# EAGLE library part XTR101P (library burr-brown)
BURR-BROWN
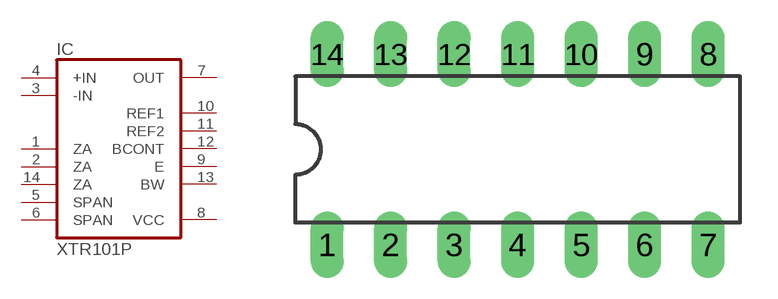
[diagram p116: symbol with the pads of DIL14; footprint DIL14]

Designator prefix IC

## XTR101P (MF: TEXAS INSTRUMENTS; MPN: XTR101AP; OC_FARNELL: 1648756; OC_NEWARK: 84K4518)  [DIL14]
1  ZA  pas
2  ZA  pas
3  -IN  in
4  +IN  in
5  SPAN  pwr
6  SPAN  pwr
7  OUT  out
8  VCC  pwr
9  E  pas
10  REF1  out
11  REF2  out
12  BCONT  out
13  BW  pas
14  ZA  pwr

## Footprint DIL14 (pad centres in mm)
Dual In Line Package
drill 0.813 long: 1 -7.62,-3.81; 2 -5.08,-3.81; 3 -2.54,-3.81; 4 0,-3.81; 5 2.54,-3.81; 6 5.08,-3.81; 7 7.62,-3.81; 8 7.62,3.81; 9 5.08,3.81; 10 2.54,3.81; 11 0,3.81; 12 -2.54,3.81; 13 -5.08,3.81; 14 -7.62,3.81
